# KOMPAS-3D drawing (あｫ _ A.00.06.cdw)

Views: Спереди 1, Спереди, Проекционный вид 2, Проекционный вид 3, Изометрия XYZ 4, Изометрия XYZ
Referenced files in C:\Users\s.slezkin\Desktop\Раскатчик арок 2\: Вал _ A.00.06.m3d
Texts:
  Вал
  http://vk.com/sergey_krd
  Левая
  Сталь 40Х  ГОСТ 4543-71
Dimensions and other numbers on the sheet: 20; 160; 16; 12; 8,5; 11; 10; 2; 3; 1; 8; 17; 1:1; 0,18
